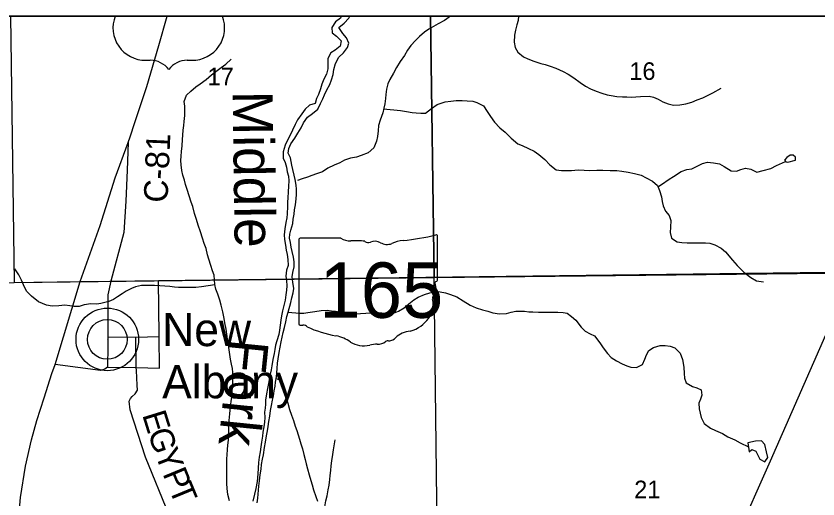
# Model space of a CAD drawing. Extents: x 0 to 34, y 0 to 22.
# Drawn here: x 6.351 to 8.257, y 19.751 to 20.9 of the extents above; entities that cross this region are included whole.
import ezdxf

# ---------------------------------------------------------------- set-up
doc = ezdxf.new("R2010")
doc.units = 0
for name, color, linetype in [('GM_X_Corporation_Text', 7, 'Continuous'), ('GM_X_County_Road', 7, 'Continuous'), ('GM_X_County_Road_Text', 7, 'Continuous'), ('GM_X_Minor_Lake', 7, 'Continuous'), ('GM_X_Minor_River', 7, 'Continuous'), ('GM_X_Minor_River_Text', 7, 'Continuous'), ('GM_X_Rail_Line', 7, 'Continuous'), ('GM_X_Section', 7, 'Continuous'), ('GM_X_Section_Text', 7, 'Continuous'), ('GM_X_State_Location', 7, 'Continuous'), ('GM_X_State_Route', 7, 'Continuous'), ('GM_X_State_Shield', 7, 'Continuous'), ('GM_X_Township_Road', 7, 'Continuous'), ('GM_X_Township_Road_Text', 7, 'Continuous'), ('GM_X_Unincorporated', 7, 'Continuous'), ('GM_X_Unincorporated_Location', 7, 'Continuous'), ('GM_X_Unincorporated_Text', 7, 'Continuous'), ('GM_X_US_Location', 7, 'Continuous'), ('GM_X_US_Route', 7, 'Continuous'), ('SH_Cut_Line', 7, 'Continuous'), ('SH_Data', 7, 'Continuous')]:
    doc.layers.add(name, color=color, linetype=linetype)

msp = doc.modelspace()

# ---------------------------------------------------------------- linework, layer by layer
at = {"layer": 'GM_X_Corporation_Text'}
for p, q in [((6.8412, 20.9), (6.5866, 20.9)), ((6.659, 20.7947), (6.6699, 20.7947)), ((6.7578, 20.7947), (6.7688, 20.7947))]:
    msp.add_line(p, q, dxfattribs=at)
for centre, radius, start, end in [((6.6581, 20.8716), 0.0769, 158.3675, 270.6383), ((6.7697, 20.8716), 0.0769, 269.3617, 21.6325), ((6.6699, 20.7398), 0.0549, 36.8699, 90), ((6.7578, 20.7398), 0.0549, 90, 143.1301)]:
    msp.add_arc(centre, radius, start, end, dxfattribs=at)
at = {"layer": 'GM_X_County_Road'}
for points in [[(6.6173, 20.599), (6.6152, 20.5333), (6.6114, 20.4591), (6.6069, 20.3848), (6.5764, 20.2689), (6.5693, 20.2362), (6.5689, 20.1357), (6.5687, 20.1153)], [(7.8996, 19.2895), (8.1438, 19.8412), (8.341, 20.2911)], [(6.5687, 20.1153), (6.5681, 20.0644), (6.5615, 20.06), (6.5513, 20.0564), (6.4436, 20.0706)]]:
    msp.add_lwpolyline(points, dxfattribs=at)
at = {"layer": 'GM_X_Minor_Lake'}
for points in [[(8.1851, 20.5522), (8.2032, 20.5566), (8.2035, 20.5643), (8.1981, 20.5691), (8.1909, 20.569), (8.1826, 20.5635)], [(8.1826, 20.5635), (8.1777, 20.557), (8.1806, 20.553), (8.1851, 20.5522)], [(8.0933, 19.863), (8.1001, 19.8688), (8.1092, 19.8648), (8.1187, 19.8452), (8.1309, 19.839), (8.138, 19.8497), (8.1347, 19.8629), (8.131, 19.8807), (8.1229, 19.889), (8.1088, 19.8887), (8.0899, 19.8842)], [(8.0899, 19.8842), (8.0933, 19.863)]]:
    msp.add_lwpolyline(points, dxfattribs=at)
at = {"layer": 'GM_X_Minor_River'}
for points in [[(7.1242, 20.9), (7.1221, 20.8951), (7.1102, 20.8858), (7.1013, 20.8724), (7.1019, 20.8598), (7.1122, 20.8517), (7.1234, 20.8412), (7.1214, 20.8286), (7.1094, 20.8189), (7.0988, 20.8123), (7.0919, 20.7993), (7.0917, 20.7845), (7.0915, 20.7742), (7.0887, 20.7616), (7.0824, 20.7501), (7.0777, 20.7375), (7.0741, 20.7268), (7.0694, 20.7134), (7.0653, 20.7039), (7.0614, 20.6917), (7.0481, 20.6876), (7.0377, 20.678), (7.0299, 20.6676), (7.0199, 20.6526), (7.014, 20.6419), (7.0078, 20.6285), (7.0023, 20.6162), (6.9953, 20.6028), (6.9905, 20.5925), (6.9858, 20.5772), (6.9861, 20.562), (6.9904, 20.5515), (6.9933, 20.5405), (6.9954, 20.5295), (6.9986, 20.5189), (6.9991, 20.5079), (6.9986, 20.4954), (6.9973, 20.4817), (6.9968, 20.4672), (6.9962, 20.457), (6.9964, 20.4467), (6.9955, 20.4296), (6.9941, 20.4201), (6.9917, 20.4083), (6.9893, 20.3934), (6.9884, 20.3793), (6.9889, 20.3683), (6.9914, 20.3547), (6.9931, 20.3426), (6.9952, 20.3323), (6.9969, 20.321), (6.9972, 20.3062), (6.9939, 20.2951), (6.9923, 20.2806), (6.9936, 20.2704), (6.9942, 20.2579), (6.9936, 20.248), (6.9922, 20.2369), (6.9902, 20.2236), (6.9881, 20.2141), (6.9842, 20.1981), (6.9817, 20.1866), (6.9804, 20.1763), (6.9786, 20.1645), (6.977, 20.1524), (6.9752, 20.1421), (6.9709, 20.1272), (6.9677, 20.1165), (6.9656, 20.1066), (6.9642, 20.0967), (6.9614, 20.0826), (6.9586, 20.0677), (6.9573, 20.0578), (6.9552, 20.0479), (6.9527, 20.0353), (6.951, 20.0258), (6.9481, 20.0136), (6.9457, 20.0006), (6.944, 19.9862), (6.9434, 19.9763), (6.9428, 19.9668), (6.9415, 19.9573), (6.9421, 19.9444), (6.9415, 19.9337), (6.9394, 19.9223), (6.9373, 19.9101), (6.9364, 19.9002), (6.9339, 19.8857), (6.9326, 19.8747), (6.9309, 19.8632), (6.9288, 19.8503), (6.9271, 19.8377), (6.9266, 19.8237), (6.9257, 19.8107), (6.9237, 19.7925), (6.9206, 19.7757), (6.9178, 19.7624), (6.9139, 19.7459)], [(6.9251, 19.7526), (6.9271, 19.772), (6.9277, 19.7815), (6.9294, 19.7937), (6.9311, 19.8085), (6.9331, 19.8215), (6.9344, 19.8325), (6.9365, 19.8455), (6.939, 19.8554), (6.9417, 19.8733), (6.9438, 19.8859), (6.9462, 19.9011), (6.9483, 19.9129), (6.95, 19.9232), (6.9517, 19.9354), (6.9538, 19.948), (6.9555, 19.9613), (6.9583, 19.9735), (6.9604, 19.9857), (6.9625, 19.9956), (6.9645, 20.0082), (6.9663, 20.0192), (6.9676, 20.0287), (6.9697, 20.0417), (6.9707, 20.0512), (6.9713, 20.0611), (6.9726, 20.074), (6.9739, 20.0843), (6.9759, 20.0992), (6.9784, 20.1121), (6.9808, 20.1243), (6.9837, 20.1361), (6.9858, 20.1468), (6.9886, 20.1586), (6.9918, 20.172), (6.9946, 20.1846), (6.9979, 20.1956), (7.0036, 20.2185), (7.0064, 20.2296), (7.0093, 20.241), (7.011, 20.2513), (7.0088, 20.2665), (7.0071, 20.2794), (7.0088, 20.2896), (7.0116, 20.303), (7.0118, 20.3148), (7.0105, 20.3265), (7.0072, 20.3394), (7.0044, 20.35), (7.0031, 20.361), (7.001, 20.3716), (7.0012, 20.3811), (7.0041, 20.3906), (7.0084, 20.4059), (7.0098, 20.4165), (7.0115, 20.4283), (7.0128, 20.439), (7.0149, 20.4504), (7.0165, 20.4649), (7.0175, 20.4756), (7.0173, 20.4881), (7.0164, 20.4976), (7.0143, 20.5112), (7.0118, 20.521), (7.0085, 20.535), (7.0061, 20.5449), (7.0032, 20.5627), (6.9973, 20.5736), (6.999, 20.585), (7.0041, 20.5958), (7.0134, 20.6096), (7.0204, 20.6215), (7.0282, 20.6341), (7.0344, 20.6456), (7.0433, 20.6591), (7.0557, 20.668), (7.0684, 20.6785), (7.0747, 20.6915), (7.0798, 20.703), (7.0842, 20.7126), (7.0893, 20.724), (7.0963, 20.7371), (7.1007, 20.7478), (7.1042, 20.7611), (7.106, 20.7729), (7.1103, 20.7867), (7.118, 20.8024), (7.1292, 20.8124), (7.1389, 20.8248), (7.1414, 20.8354), (7.1366, 20.8483), (7.1273, 20.8588), (7.1184, 20.8723), (7.1307, 20.8831), (7.1419, 20.8947), (7.1444, 20.9)], [(7.3839, 20.9), (7.3836, 20.8998), (7.3694, 20.8897), (7.354, 20.8811), (7.3434, 20.8748), (7.3318, 20.8686), (7.322, 20.8616), (7.3097, 20.8511), (7.2999, 20.8418), (7.2891, 20.8295), (7.281, 20.8184), (7.274, 20.8061)], [(7.5447, 20.9), (7.5444, 20.8892), (7.5415, 20.8793), (7.5379, 20.8663), (7.5359, 20.8548), (7.5346, 20.8377), (7.5371, 20.8249), (7.5437, 20.8136), (7.5572, 20.8028), (7.5672, 20.798), (7.5817, 20.7925), (7.5985, 20.7871), (7.6088, 20.7846), (7.6202, 20.781), (7.634, 20.7756), (7.6512, 20.7679), (7.6634, 20.7616), (7.6765, 20.7527), (7.6915, 20.7416), (7.7041, 20.7334), (7.7164, 20.7268), (7.7294, 20.7213), (7.7431, 20.7166), (7.7561, 20.7126), (7.7656, 20.7105), (7.779, 20.7088), (7.7919, 20.7075), (7.8029, 20.7073), (7.8135, 20.7071), (7.8238, 20.708), (7.8348, 20.7086), (7.8553, 20.7089), (7.8663, 20.7068), (7.877, 20.7021), (7.8881, 20.6954), (7.9011, 20.6907), (7.9133, 20.6882), (7.9289, 20.6889), (7.9425, 20.691), (7.9569, 20.695), (7.9697, 20.7002), (7.9832, 20.7057), (7.9942, 20.7105), (8.0074, 20.7171), (8.0269, 20.7281)], [(6.8581, 19.7466), (6.8544, 19.7617), (6.8526, 19.7757), (6.8521, 19.7875), (6.8519, 19.7989), (6.8521, 19.8099), (6.8519, 19.8224), (6.852, 19.8338), (6.8522, 19.846), (6.8524, 19.8555), (6.8534, 19.8688), (6.8543, 19.8791), (6.8557, 19.8905), (6.8562, 19.9023), (6.8568, 19.9137), (6.8566, 19.9247), (6.8572, 19.9373), (6.8588, 19.9532), (6.8608, 19.9704), (6.8621, 19.9825), (6.8634, 19.9932), (6.8644, 20.005), (6.8653, 20.0179), (6.8659, 20.0274), (6.8661, 20.0404), (6.8659, 20.0521), (6.865, 20.0616), (6.8629, 20.0718), (6.8604, 20.0836), (6.8587, 20.0946), (6.8574, 20.1056), (6.8557, 20.1177), (6.8536, 20.131), (6.8518, 20.1431), (6.8501, 20.1552), (6.8472, 20.17), (6.8455, 20.1806), (6.8426, 20.1961), (6.8385, 20.2116), (6.8353, 20.2237), (6.8301, 20.2381), (6.8258, 20.2498), (6.8233, 20.2615), (6.8214, 20.2831), (6.8174, 20.2937), (6.8138, 20.3062), (6.8094, 20.3213), (6.8062, 20.3319), (6.8025, 20.3467), (6.7981, 20.3587), (6.7937, 20.3716), (6.7889, 20.3863), (6.7837, 20.4022), (6.7797, 20.4158), (6.7753, 20.4302), (6.7709, 20.4464), (6.7673, 20.457), (6.7624, 20.4725), (6.7577, 20.4869), (6.7537, 20.4993), (6.7508, 20.5092), (6.7476, 20.5216), (6.7451, 20.5322), (6.743, 20.5459), (6.7425, 20.5561), (6.743, 20.5664), (6.7444, 20.5778), (6.7453, 20.5907), (6.7462, 20.606), (6.7472, 20.6162), (6.7481, 20.628), (6.7494, 20.6394), (6.7504, 20.6493), (6.7517, 20.663), (6.7519, 20.6737), (6.7517, 20.6858), (6.7507, 20.6968), (6.7558, 20.7113), (6.7659, 20.7214), (6.7783, 20.7315), (6.7888, 20.7388), (6.8023, 20.7486), (6.815, 20.7602), (6.8255, 20.7683), (6.8386, 20.7777), (6.8491, 20.7858), (6.8618, 20.797)], [(7.274, 20.8061), (7.2639, 20.7919), (7.2554, 20.7777), (7.2477, 20.7642), (7.2392, 20.7493), (7.2348, 20.7386), (7.2316, 20.726), (7.2299, 20.7134), (7.229, 20.7035), (7.2273, 20.6914), (7.2248, 20.6807), (7.2227, 20.6696), (7.2162, 20.652), (7.2122, 20.6391), (7.2113, 20.6269), (7.2096, 20.6136), (7.2075, 20.6025), (7.2009, 20.5865), (7.1874, 20.5748), (7.1709, 20.5677), (7.1599, 20.5641), (7.1459, 20.5616), (7.1316, 20.5568), (7.1203, 20.5509), (7.1067, 20.5454), (7.092, 20.5376), (7.0793, 20.5294), (7.0649, 20.5242), (7.054, 20.5206), (7.0438, 20.5166), (7.0306, 20.5126), (7.02, 20.5086)], [(7.2245, 20.6791), (7.2647, 20.6753), (7.2792, 20.6728), (7.2925, 20.6708), (7.302, 20.6698), (7.3131, 20.6688), (7.3241, 20.669), (7.3379, 20.6803), (7.3518, 20.6892), (7.3707, 20.6956), (7.384, 20.6977), (7.3968, 20.6987), (7.4109, 20.6989), (7.4234, 20.6984), (7.4364, 20.6971), (7.4463, 20.6942), (7.4616, 20.6865), (7.4709, 20.673), (7.4787, 20.6606), (7.4884, 20.6478), (7.5008, 20.6343), (7.5131, 20.6235), (7.5278, 20.6097), (7.5436, 20.5959), (7.5535, 20.5919), (7.5688, 20.5849), (7.5822, 20.5783), (7.5937, 20.5705), (7.6076, 20.5586), (7.6196, 20.5459), (7.6346, 20.534), (7.6471, 20.5323), (7.671, 20.5327), (7.6873, 20.5341), (7.701, 20.5335), (7.7147, 20.5326), (7.731, 20.5329), (7.7458, 20.5328), (7.7633, 20.5327), (7.7785, 20.5325), (7.791, 20.5312), (7.8059, 20.5288), (7.8211, 20.5253), (7.8364, 20.521), (7.8486, 20.5147), (7.8639, 20.507), (7.8751, 20.4965), (7.8802, 20.4848), (7.8847, 20.4697), (7.8868, 20.4583), (7.8888, 20.4485), (7.8947, 20.4353), (7.9029, 20.4252), (7.9069, 20.4131), (7.9064, 20.3979), (7.9058, 20.3846), (7.9091, 20.3713), (7.9225, 20.3628), (7.9332, 20.3607), (7.9457, 20.3602), (7.9624, 20.3601), (7.9894, 20.3605), (8, 20.3592), (8.0118, 20.3559), (8.0268, 20.3474), (8.0372, 20.3385), (8.0538, 20.319), (8.0647, 20.3067), (8.0809, 20.2906), (8.097, 20.2776), (8.1112, 20.2702), (8.1272, 20.2678)], [(7.8764, 20.4937), (7.8849, 20.4993), (7.9033, 20.5114), (7.9139, 20.5184), (7.9315, 20.5301), (7.9455, 20.5345), (7.9572, 20.5366), (7.9821, 20.5492), (7.9941, 20.5524), (8.0086, 20.5508), (8.0227, 20.548), (8.0342, 20.5421), (8.0503, 20.5313), (8.0632, 20.5308), (8.0738, 20.5351), (8.0844, 20.538), (8.0977, 20.5352), (8.1115, 20.5282), (8.127, 20.5322), (8.1447, 20.5374), (8.1587, 20.5441), (8.1801, 20.5537)], [(6.8235, 20.2607), (6.7915, 20.2553), (6.7782, 20.2539), (6.7627, 20.2537), (6.7528, 20.2539), (6.7372, 20.2537), (6.7277, 20.255), (6.7167, 20.256), (6.7042, 20.2573), (6.6924, 20.2579), (6.6798, 20.2588), (6.6703, 20.2586), (6.6608, 20.2589), (6.6487, 20.2587), (6.6351, 20.2558), (6.6249, 20.2518), (6.6129, 20.2455), (6.6031, 20.2389), (6.5918, 20.2315), (6.5821, 20.2257), (6.5715, 20.2205), (6.5526, 20.2157), (6.5428, 20.2147), (6.5287, 20.2149), (6.5128, 20.2131), (6.5011, 20.2091), (6.4882, 20.2085), (6.4787, 20.2103), (6.4665, 20.2116), (6.4521, 20.2102), (6.4366, 20.2092), (6.4229, 20.2116), (6.4045, 20.2201), (6.3879, 20.2331), (6.3756, 20.2454), (6.3681, 20.2601), (6.3634, 20.2711), (6.3575, 20.2843), (6.3478, 20.2982)], [(6.9979, 20.1956), (7.0249, 20.1927), (7.0351, 20.1932), (7.0446, 20.1941), (7.0609, 20.197), (7.076, 20.1996), (7.09, 20.1998), (7.1003, 20.1988), (7.1098, 20.1978), (7.1197, 20.1961), (7.1315, 20.1944), (7.1445, 20.1927), (7.1551, 20.1914), (7.1695, 20.192), (7.1824, 20.193), (7.1945, 20.1939), (7.2067, 20.1941), (7.2204, 20.1936), (7.2352, 20.1919), (7.2477, 20.1929), (7.2602, 20.1977), (7.2733, 20.2059), (7.2845, 20.2155), (7.2965, 20.2245), (7.3067, 20.2311), (7.3218, 20.2374), (7.3342, 20.2414), (7.3471, 20.2443), (7.3592, 20.2437), (7.3718, 20.2409), (7.3836, 20.2377), (7.3985, 20.2315), (7.4135, 20.2222), (7.43, 20.2122), (7.4442, 20.2053), (7.4594, 20.2009), (7.472, 20.1977), (7.4842, 20.1938), (7.4998, 20.191), (7.5165, 20.192), (7.5278, 20.1949), (7.5388, 20.1977), (7.5502, 20.1975), (7.5597, 20.1973), (7.57, 20.1963), (7.5795, 20.1961), (7.5928, 20.1952), (7.6041, 20.195), (7.6383, 20.1955), (7.6509, 20.1942), (7.6607, 20.1929), (7.6711, 20.1851), (7.6811, 20.1761), (7.694, 20.1592), (7.7036, 20.1503), (7.7151, 20.1436), (7.7258, 20.1389), (7.7382, 20.1223), (7.746, 20.1103), (7.7565, 20.0972), (7.7654, 20.0871), (7.7784, 20.0793), (7.7915, 20.0723), (7.8022, 20.0672), (7.8121, 20.0647), (7.8254, 20.0638), (7.8401, 20.0705), (7.8452, 20.0831), (7.8492, 20.0934), (7.8547, 20.1041), (7.8656, 20.1115), (7.8815, 20.116), (7.8936, 20.1158), (7.9054, 20.1145), (7.9165, 20.1101), (7.9292, 20.0981), (7.9352, 20.0823), (7.9377, 20.0645), (7.9387, 20.0493), (7.9397, 20.0383), (7.9433, 20.0273), (7.959, 20.0181), (7.9693, 20.0156), (7.9793, 20.0104), (7.9806, 19.9979), (7.9777, 19.9884), (7.9741, 19.9785), (7.9743, 19.9655), (7.9768, 19.9549), (7.9796, 19.9447), (7.9867, 19.93), (8.0013, 19.9189), (8.0131, 19.9138), (8.0296, 19.9068), (8.0426, 19.899), (8.0591, 19.8913), (8.0717, 19.8843), (8.0914, 19.8749)], [(6.969, 20.0377), (6.9755, 20.0349), (6.9821, 20.0229), (6.9874, 20.0051), (6.991, 19.9938), (6.9965, 19.9787), (7.001, 19.9636), (7.0054, 19.9503), (7.0101, 19.9375), (7.0145, 19.9239), (7.0181, 19.9133), (7.0213, 19.9035), (7.0242, 19.8929), (7.0278, 19.8819), (7.0314, 19.8698), (7.0346, 19.8566), (7.0383, 19.8449), (7.0407, 19.8343), (7.0436, 19.8222), (7.0472, 19.8082), (7.0512, 19.7946), (7.0544, 19.7847), (7.0581, 19.7726), (7.0636, 19.7568), (7.0676, 19.7458)], [(7.0761, 19.7229), (7.0846, 19.732), (7.0874, 19.7461), (7.0902, 19.7583), (7.093, 19.7721), (7.0951, 19.7839), (7.0968, 19.7972), (7.0977, 19.8067), (7.0987, 19.8185), (7.1, 19.8296), (7.1013, 19.8414), (7.1037, 19.8562), (7.1054, 19.868), (7.1079, 19.8817), (7.1096, 19.8913)], [(6.9242, 19.7412), (6.9251, 19.7526)]]:
    msp.add_lwpolyline(points, dxfattribs=at)
at = {"layer": 'GM_X_Rail_Line'}
msp.add_lwpolyline([(8.9, 20.9), (5.4984, 20.9), (5.5102, 20.2613), (5.523, 19.2739)], dxfattribs=at)
at = {"layer": 'GM_X_Section'}
msp.add_lwpolyline([(7.3448, 20.2776), (8.3505, 20.2885), (8.3591, 19.2972), (7.3562, 19.2826)], close=True, dxfattribs=at)
at = {"layer": 'GM_X_State_Route'}
for points in [[(6.5764, 20.2689), (6.689, 20.2704), (8.341, 20.2911), (8.5527, 20.295)], [(5.7884, 20.2566), (6.3932, 20.267), (6.3942, 20.267)], [(6.3942, 20.267), (6.5033, 20.268), (6.5734, 20.2689), (6.5764, 20.2689)]]:
    msp.add_lwpolyline(points, dxfattribs=at)
at = {"layer": 'GM_X_State_Shield'}
for p, q in [((7.023, 20.3678), (7.023, 20.1677)), ((7.1228, 20.3713), (7.0262, 20.3713)), ((7.3526, 20.2716), (7.3526, 20.3762)), ((7.3525, 20.2716), (7.3526, 20.2716))]:
    msp.add_line(p, q, dxfattribs=at)
for points in [[(7.3363, 20.9), (6.3373, 20.9), (6.3461, 20.2662), (7.3448, 20.2776)], [(8.343, 20.9), (7.3363, 20.9), (7.3448, 20.2776), (8.3505, 20.2885)]]:
    msp.add_lwpolyline(points, close=True, dxfattribs=at)
for centre, major_axis, start_param, end_param in [((7.2352, 20.6441), (0.3495, 0), 4.814394, 5.042369), ((7.3489, 20.3767), (0.00367, 0), 6.141152, 7.989035), ((7.0268, 20.3683), (0.00382, 0), 1.712693, 3.28349), ((7.1457, 20.3945), (0.037, 0), 4.042523, 4.731795), ((7.158, 20.2589), (0.133, 0), 1.404758, 1.657858), ((7.1882, 20.3693), (0.0107, 0), 3.836095, 5.185415), ((7.2039, 20.3462), (0.0222, 0), 0.950623, 2.079405), ((7.2326, 20.3779), (0.0267, 0), 4.081561, 5.145723), ((7.2798, 20.3102), (0.0703, 0), 1.699011, 2.107814), ((7.3517, 20.2639), (0.00568, 0), 1.883978, 3.671073), ((7.3487, 20.2712), (0.00393, 0), 5.05454, 6.418171), ((7.3156, 20.2506), (0.0341, 0), 5.934695, 6.695948), ((7.2547, 20.2144), (0.0874, 0), 5.101752, 6.440018), ((7.3657, 20.2277), (0.0248, 0), 2.387724, 3.262537), ((7.0268, 20.1673), (0.00385, 0), 3.00124, 4.508301), ((7.0274, 20.1878), (0.0294, 0), 4.665946, 4.897461), ((7.0334, 20.1562), (0.0106, 0), 0.519207, 1.627899), ((7.1672, 20.336), (0.2524, 0), 4.195997, 4.488961), ((7.2916, 20.1115), (0.0479, 0), 1.647645, 2.488434), ((7.092, 20.0778), (0.079, 0), 0.823519, 1.323587), ((7.2309, 20.1483), (0.0282, 0), 4.937069, 5.64225), ((7.1774, 20.1552), (0.0501, 0), 4.026481, 4.996735), ((7.2063, 20.086), (0.0412, 0), 1.495662, 1.94098), ((7.21, 20.1402), (0.0267, 0), 4.691044, 5.507374), ((7.2342, 20.1208), (0.00752, 0), 1.147584, 2.315152)]:
    msp.add_ellipse(centre, major_axis=major_axis, ratio=0.8, start_param=start_param, end_param=end_param, dxfattribs=at)
at = {"layer": 'GM_X_Township_Road'}
msp.add_line((6.691, 20.1365), (6.6357, 20.1352), dxfattribs=at)
for points in [[(6.691, 20.1387), (6.691, 20.1397), (6.689, 20.2704)], [(6.5681, 20.0644), (6.6366, 20.0633), (6.6921, 20.0624), (6.691, 20.1365), (6.691, 20.1387)], [(6.847, 19.2754), (6.7841, 19.5108), (6.7657, 19.5851), (6.7546, 19.6119), (6.7446, 19.6406), (6.7149, 19.7124), (6.6581, 19.8503), (6.6219, 19.9631), (6.6196, 19.9836), (6.6226, 19.9897), (6.6271, 19.9947), (6.6338, 20.0013), (6.6398, 20.0094), (6.6388, 20.0212), (6.6367, 20.0561), (6.6366, 20.0633), (6.6357, 20.1352), (6.5689, 20.1357)]]:
    msp.add_lwpolyline(points, dxfattribs=at)
at = {"layer": 'GM_X_Unincorporated'}
for radius in [0.0744, 0.0472]:
    msp.add_circle((6.5677, 20.1304), radius, dxfattribs=at)
at = {"layer": 'GM_X_Unincorporated_Location'}
msp.add_line((6.5677, 20.1304), (6.5677, 20.1304), dxfattribs=at)
at = {"layer": 'GM_X_US_Route'}
for points in [[(6.6333, 20.6467), (6.6615, 20.7325), (6.6899, 20.8298), (6.7103, 20.9)], [(6.5033, 20.268), (6.5504, 20.4016), (6.5865, 20.5146), (6.6173, 20.599), (6.6221, 20.6123), (6.6333, 20.6467)], [(6.3555, 19.5447), (6.3555, 19.5527), (6.3562, 19.6891), (6.3615, 19.754), (6.3734, 19.8292), (6.3877, 19.8918), (6.3999, 19.9377), (6.4174, 19.9914), (6.436, 20.0494), (6.4436, 20.0706), (6.5033, 20.268)]]:
    msp.add_lwpolyline(points, dxfattribs=at)
at = {"layer": 'SH_Cut_Line'}
msp.add_lwpolyline([(8.9, 20.9), (2.1, 20.9)], dxfattribs=at)
at = {"layer": 'SH_Data'}
msp.add_line((2.1, 20.9), (8.9, 20.9), dxfattribs=at)

# ---------------------------------------------------------------- texts
at = {"layer": 'GM_X_County_Road_Text'}
msp.add_text('C-81', height=0.05682, rotation=87.6002, dxfattribs=at).set_placement((6.7108, 20.4551))
at = {"layer": 'GM_X_Minor_River_Text'}
for s, height, rotation, p in [('Middle', 0.09474, 270.7547, (6.8656, 20.7214)), ('Fork', 0.09475, 264.1985, (6.8576, 20.1342))]:
    msp.add_text(s, height=height, rotation=rotation, dxfattribs=at).set_placement(p)
at = {"layer": 'GM_X_Section_Text'}
for s, p in [('17', (6.806, 20.7352)), ('16', (7.8085, 20.748)), ('21', (7.8201, 19.7525))]:
    msp.add_text(s, height=0.04186, rotation=0, dxfattribs=at).set_placement(p)
at = {"layer": 'GM_X_State_Location'}
for s in ['s', 'r']:
    msp.add_text(s, height=0.000189, dxfattribs=at).set_placement((7.1841, 20.2545))
msp.add_text('165', height=0.000189, rotation=0, dxfattribs=at).set_placement((7.1172, 20.2407))
at = {"layer": 'GM_X_State_Shield'}
msp.add_text('165', height=0.13184, dxfattribs=at).set_placement((7.0721, 20.1818))
at = {"layer": 'GM_X_Township_Road_Text'}
for s, rotation, p in [('E', 287.2206, (6.6502, 19.9512)), ('G', 288.3224, (6.6632, 19.9095)), ('Y', 291.1098, (6.6799, 19.8592)), ('P', 292.4513, (6.6985, 19.8112)), ('T', 292.4564, (6.7131, 19.7757))]:
    msp.add_text(s, height=0.0568, rotation=rotation, dxfattribs=at).set_placement(p)
at = {"layer": 'GM_X_Unincorporated_Text'}
for s, p in [('New', (6.6981, 20.1145)), ('Albany', (6.6981, 19.9904))]:
    msp.add_text(s, height=0.07898, rotation=0, dxfattribs=at).set_placement(p)
at = {"layer": 'GM_X_US_Location'}
msp.add_text('62', height=0.000189, rotation=0, dxfattribs=at).set_placement((6.6747, 20.8699))

doc.saveas('drawing.dxf')
